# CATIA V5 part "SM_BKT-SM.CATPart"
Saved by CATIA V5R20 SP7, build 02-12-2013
Part number: SM_BKT
Bounding box of the stored display mesh (mm): x 0 to 209, y -20 to 253.614, z 0 to 209
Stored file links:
  C:\Users\CAS-\Desktop\Exercise Files\SM_BKT-SM.CATPart
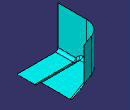
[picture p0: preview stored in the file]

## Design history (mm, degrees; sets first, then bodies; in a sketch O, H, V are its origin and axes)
Set1 "CONST_GEO"
  Point1: type OnCurve, Support Sketch1, Length 10
Set2 "Inputs"
  Sketch1 "Flange Sketch" on xy-plane, origin (0, 0, 0), H (1, 0, 0), V (0, 1, 0)
    point P1 (0, -20)
    line L1 (0, -20) -> (0, 125)
    arc A1 centre (90, 125) radius 90 from (0, 125) to (59.2182, 209.5723) cw
    point P3 (90, 125)
    line L2 (59.2182, 209.5723) -> (120.2982, 231.8036)
    radius A1 = 90
    distance H P3 = 125
    angle L1 L2 = 110
    length L2 = 65
    distance H P1 = 20
    coincidence: P1 V
    vertical: L1 V
    tangency: A1 L1, A1 L2
  Sketch2 "Main Body Sketch" on yz-plane, origin (0, 0, 0), H (0, 1, 0), V (0, 0, 1)
    point P1 (-20, 0)
    line L1 (-20, 0) -> (75, 0)
    point P2 (75, 0)
    line L2 (75, 0) -> (100, 25)
    line L3 (100, 25) -> (275, 25)
    reference intersected line E1 through (0, 0) direction (0, 1) from zx-plane
    distance V P1 = 20
    angle L1 L2 = 45
    distance L1 L3 = 25
    distance E1 P2 = 75
    length L3 = 175
    horizontal: L1 H, L3 H
    coincidence: H L1
Set3 "Spliting Elements"
  Plane1: type Normal, Curve Sketch1, RefPoint Point1
Set4 "Operations"
  Extrude1 "Slab-1": Lim1 209, Lim2 87, Element1 Sketch2
  Extrude2 "Slab-2": Lim1 209, Lim2 87, Element1 Sketch1
  Fillet1: radius 13, on edge [face of Extrude1 from Sketch2.L2 | face of Extrude1 from Sketch2.L1]
  Fillet2: radius 10, on edge [face of Extrude1 from Sketch2.L3 | face of Extrude1 from Sketch2.L2]
  Fillet3 "Main-Body": type BiTangent, Element1 Extrude2, Element2 Fillet2, Radius 13
Body1 (main body)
